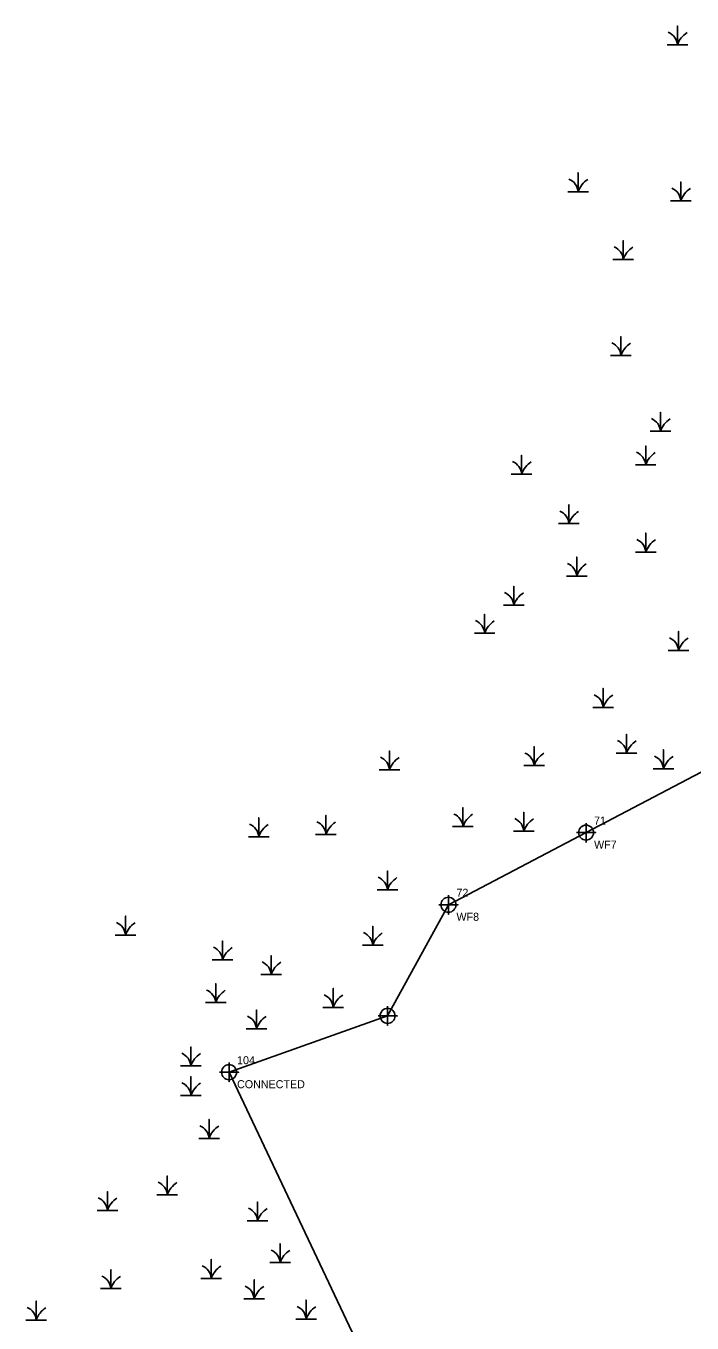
# Model space of a CAD drawing. Extents: x 2189822 to 2190837, y 387253 to 388663.
# Drawn here: x 2189966.4 to 2190174.5, y 387688.6 to 388093.7 of the extents above; entities that cross this region are included whole.
import ezdxf

# ---------------------------------------------------------------- set-up
doc = ezdxf.new("R2010")
doc.units = 0
for name, color, linetype in [('COGO Default Chain', 7, 'Continuous'), ('DTM Contours Major', 7, 'Continuous'), ('DTM Contours Minor', 7, 'Continuous'), ('Exist DTM Breakline Cogo Elevation', 7, 'Continuous'), ('Exist DTM Breakline Cogo Number', 7, 'Continuous')]:
    doc.layers.add(name, color=color, linetype=linetype)

msp = doc.modelspace()

# ---------------------------------------------------------------- linework, layer by layer
at = {"layer": 'DTM Contours Major'}
for points in [[(2190141.4, 387844.78), (2190141.4, 387838.78), (2190141.4, 387841.78), (2190144.4, 387841.78), (2190138.4, 387841.78)], [(2190098.41, 387822.25), (2190098.41, 387816.25), (2190098.41, 387819.25), (2190101.41, 387819.25), (2190095.41, 387819.25)], [(2190079.41, 387787.56), (2190079.41, 387781.56), (2190079.41, 387784.56), (2190082.41, 387784.56), (2190076.41, 387784.56)], [(2190029.88, 387769.97), (2190029.88, 387763.97), (2190029.88, 387766.97), (2190032.88, 387766.97), (2190026.88, 387766.97)]]:
    msp.add_lwpolyline(points, dxfattribs=at)
for centre in [(2190141.4, 387841.78), (2190098.41, 387819.25), (2190079.41, 387784.56), (2190029.88, 387766.97)]:
    msp.add_circle(centre, 2.34, dxfattribs=at)
at = {"layer": 'Exist DTM Breakline Cogo Elevation'}
for p, q in [((2190169.93, 388090.44), (2190169.93, 388090.44)), ((2190138.9, 388044.58), (2190138.9, 388044.58)), ((2190170.98, 388041.76), (2190170.98, 388041.76)), ((2190153, 388023.42), (2190153, 388023.42)), ((2190152.3, 387993.43), (2190152.3, 387993.43)), ((2190164.64, 387969.8), (2190164.64, 387969.8)), ((2190160.02, 387959.29), (2190160.02, 387959.29)), ((2190121.28, 387956.39), (2190121.28, 387956.39)), ((2190136.05, 387940.94), (2190136.05, 387940.94)), ((2190160.06, 387932.05), (2190160.06, 387932.05)), ((2190138.47, 387924.57), (2190138.47, 387924.57)), ((2190118.81, 387915.48), (2190118.81, 387915.48)), ((2190109.72, 387906.71), (2190109.72, 387906.71)), ((2190170.28, 387901.37), (2190170.28, 387901.37)), ((2190146.73, 387883.57), (2190146.73, 387883.57)), ((2190154.06, 387869.26), (2190154.06, 387869.26)), ((2190079.98, 387864.06), (2190079.98, 387864.06)), ((2190125.16, 387865.38), (2190125.16, 387865.38)), ((2190165.57, 387864.39), (2190165.57, 387864.39)), ((2190102.95, 387846.34), (2190102.95, 387846.34)), ((2190039.14, 387843.16), (2190039.14, 387843.16)), ((2190060.16, 387843.9), (2190060.16, 387843.9)), ((2190121.95, 387844.89), (2190121.95, 387844.89)), ((2190079.33, 387826.58), (2190079.33, 387826.58)), ((2189997.54, 387812.47), (2189997.54, 387812.47)), ((2190074.74, 387809.3), (2190074.74, 387809.3)), ((2190027.86, 387804.71), (2190027.86, 387804.71)), ((2190043.02, 387800.13), (2190043.02, 387800.13)), ((2190025.71, 387791.38), (2190025.71, 387791.38)), ((2190062.41, 387789.9), (2190062.41, 387789.9)), ((2190038.43, 387783.19), (2190038.43, 387783.19)), ((2190017.95, 387771.62), (2190017.95, 387771.62)), ((2190017.99, 387762.38), (2190017.99, 387762.38)), ((2190023.63, 387748.98), (2190023.63, 387748.98)), ((2190010.58, 387731.34), (2190010.58, 387731.34)), ((2189991.86, 387726.47), (2189991.86, 387726.47)), ((2190038.79, 387723.23), (2190038.79, 387723.23)), ((2190045.84, 387710.17), (2190045.84, 387710.17)), ((2190024.33, 387705.24), (2190024.33, 387705.24)), ((2189992.96, 387702.06), (2189992.96, 387702.06)), ((2190037.73, 387698.89), (2190037.73, 387698.89)), ((2189969.65, 387692.25), (2189969.65, 387692.25)), ((2190053.95, 387692.54), (2190053.95, 387692.54))]:
    msp.add_line(p, q, dxfattribs=at)
for points in [[(2190166.7, 388087.77), (2190169.93, 388087.77), (2190169.93, 388093.68), (2190169.93, 388087.77), (2190173.15, 388087.77)], [(2190135.68, 388041.91), (2190138.9, 388041.91), (2190138.9, 388047.83), (2190138.9, 388041.91), (2190142.13, 388041.91)], [(2190167.76, 388039.09), (2190170.98, 388039.09), (2190170.98, 388045), (2190170.98, 388039.09), (2190174.21, 388039.09)], [(2190149.78, 388020.74), (2190153.01, 388020.74), (2190153.01, 388026.66), (2190153.01, 388020.74), (2190156.23, 388020.74)], [(2190149.07, 387990.76), (2190152.3, 387990.76), (2190152.3, 387996.68), (2190152.3, 387990.76), (2190155.53, 387990.76)], [(2190161.41, 387967.12), (2190164.64, 387967.12), (2190164.64, 387973.04), (2190164.64, 387967.12), (2190167.86, 387967.12)], [(2190118.05, 387953.72), (2190121.28, 387953.72), (2190121.28, 387959.64), (2190121.28, 387953.72), (2190124.5, 387953.72)], [(2190156.79, 387956.61), (2190160.02, 387956.61), (2190160.02, 387962.53), (2190160.02, 387956.61), (2190163.24, 387956.61)], [(2190132.82, 387938.27), (2190136.05, 387938.27), (2190136.05, 387944.19), (2190136.05, 387938.27), (2190139.27, 387938.27)], [(2190156.83, 387929.38), (2190160.06, 387929.38), (2190160.06, 387935.3), (2190160.06, 387929.38), (2190163.28, 387929.38)], [(2190135.25, 387921.89), (2190138.47, 387921.89), (2190138.47, 387927.81), (2190138.47, 387921.89), (2190141.7, 387921.89)], [(2190115.59, 387912.8), (2190118.81, 387912.8), (2190118.81, 387918.72), (2190118.81, 387912.8), (2190122.04, 387912.8)], [(2190106.5, 387904.04), (2190109.72, 387904.04), (2190109.72, 387909.96), (2190109.72, 387904.04), (2190112.95, 387904.04)], [(2190167.05, 387898.69), (2190170.28, 387898.69), (2190170.28, 387904.61), (2190170.28, 387898.69), (2190173.5, 387898.69)], [(2190143.51, 387880.9), (2190146.73, 387880.9), (2190146.73, 387886.81), (2190146.73, 387880.9), (2190149.96, 387880.9)], [(2190150.84, 387866.59), (2190154.06, 387866.59), (2190154.06, 387872.51), (2190154.06, 387866.59), (2190157.29, 387866.59)], [(2190076.76, 387861.39), (2190079.98, 387861.39), (2190079.98, 387867.31), (2190079.98, 387861.39), (2190083.21, 387861.39)], [(2190121.93, 387862.71), (2190125.16, 387862.71), (2190125.16, 387868.63), (2190125.16, 387862.71), (2190128.38, 387862.71)], [(2190162.34, 387861.72), (2190165.57, 387861.72), (2190165.57, 387867.64), (2190165.57, 387861.72), (2190168.79, 387861.72)], [(2190099.72, 387843.66), (2190102.95, 387843.66), (2190102.95, 387849.58), (2190102.95, 387843.66), (2190106.17, 387843.66)], [(2190035.91, 387840.49), (2190039.14, 387840.49), (2190039.14, 387846.4), (2190039.14, 387840.49), (2190042.37, 387840.49)], [(2190056.93, 387841.22), (2190060.16, 387841.22), (2190060.16, 387847.14), (2190060.16, 387841.22), (2190063.38, 387841.22)], [(2190118.72, 387842.21), (2190121.95, 387842.21), (2190121.95, 387848.13), (2190121.95, 387842.21), (2190125.18, 387842.21)], [(2190076.1, 387823.91), (2190079.33, 387823.91), (2190079.33, 387829.83), (2190079.33, 387823.91), (2190082.55, 387823.91)], [(2189994.32, 387809.8), (2189997.54, 387809.8), (2189997.54, 387815.72), (2189997.54, 387809.8), (2190000.77, 387809.8)], [(2190071.52, 387806.62), (2190074.75, 387806.62), (2190074.75, 387812.54), (2190074.75, 387806.62), (2190077.97, 387806.62)], [(2190024.63, 387802.04), (2190027.86, 387802.04), (2190027.86, 387807.95), (2190027.86, 387802.04), (2190031.08, 387802.04)], [(2190039.79, 387797.45), (2190043.02, 387797.45), (2190043.02, 387803.37), (2190043.02, 387797.45), (2190046.24, 387797.45)], [(2190022.48, 387788.7), (2190025.71, 387788.7), (2190025.71, 387794.62), (2190025.71, 387788.7), (2190028.93, 387788.7)], [(2190059.18, 387787.22), (2190062.41, 387787.22), (2190062.41, 387793.14), (2190062.41, 387787.22), (2190065.63, 387787.22)], [(2190035.21, 387780.52), (2190038.43, 387780.52), (2190038.43, 387786.44), (2190038.43, 387780.52), (2190041.66, 387780.52)], [(2190014.73, 387768.95), (2190017.95, 387768.95), (2190017.95, 387774.86), (2190017.95, 387768.95), (2190021.18, 387768.95)], [(2190014.76, 387759.71), (2190017.99, 387759.71), (2190017.99, 387765.62), (2190017.99, 387759.71), (2190021.21, 387759.71)], [(2190020.4, 387746.3), (2190023.63, 387746.3), (2190023.63, 387752.22), (2190023.63, 387746.3), (2190026.85, 387746.3)], [(2190007.36, 387728.66), (2190010.59, 387728.66), (2190010.59, 387734.58), (2190010.59, 387728.66), (2190013.81, 387728.66)], [(2189988.64, 387723.79), (2189991.86, 387723.79), (2189991.86, 387729.71), (2189991.86, 387723.79), (2189995.09, 387723.79)], [(2190035.56, 387720.55), (2190038.79, 387720.55), (2190038.79, 387726.47), (2190038.79, 387720.55), (2190042.01, 387720.55)], [(2190042.61, 387707.5), (2190045.84, 387707.5), (2190045.84, 387713.42), (2190045.84, 387707.5), (2190049.06, 387707.5)], [(2190021.11, 387702.56), (2190024.33, 387702.56), (2190024.33, 387708.48), (2190024.33, 387702.56), (2190027.56, 387702.56)], [(2189989.73, 387699.39), (2189992.96, 387699.39), (2189992.96, 387705.3), (2189992.96, 387699.39), (2189996.18, 387699.39)], [(2190034.5, 387696.21), (2190037.73, 387696.21), (2190037.73, 387702.13), (2190037.73, 387696.21), (2190040.96, 387696.21)], [(2190050.72, 387689.86), (2190053.95, 387689.86), (2190053.95, 387695.78), (2190053.95, 387689.86), (2190057.17, 387689.86)], [(2189966.43, 387689.58), (2189969.66, 387689.58), (2189969.66, 387695.5), (2189969.66, 387689.58), (2189972.88, 387689.58)]]:
    msp.add_lwpolyline(points, dxfattribs=at)
for centre, radius, start, end in [((2190165.33, 388087.43), 4.61, 4.1403, 67.535), ((2190176.77, 388085.49), 7.21, 122.1274, 161.6222), ((2190134.3, 388041.57), 4.61, 4.1403, 67.535), ((2190145.75, 388039.64), 7.21, 122.1274, 161.6222), ((2190166.38, 388038.75), 4.61, 4.1403, 67.535), ((2190177.83, 388036.81), 7.21, 122.1274, 161.6222), ((2190148.41, 388020.41), 4.61, 4.1403, 67.535), ((2190159.85, 388018.47), 7.21, 122.1274, 161.6222), ((2190147.7, 387990.43), 4.61, 4.1403, 67.535), ((2190159.14, 387988.49), 7.21, 122.1274, 161.6222), ((2190160.04, 387966.79), 4.61, 4.1403, 67.535), ((2190171.48, 387964.85), 7.21, 122.1274, 161.6222), ((2190155.42, 387956.28), 4.61, 4.1403, 67.535), ((2190166.86, 387954.34), 7.21, 122.1274, 161.6222), ((2190116.68, 387953.39), 4.61, 4.1403, 67.535), ((2190128.12, 387951.45), 7.21, 122.1274, 161.6222), ((2190131.45, 387937.93), 4.61, 4.1403, 67.535), ((2190142.89, 387936), 7.21, 122.1274, 161.6222), ((2190155.46, 387929.05), 4.61, 4.1403, 67.535), ((2190166.9, 387927.11), 7.21, 122.1274, 161.6222), ((2190133.87, 387921.56), 4.61, 4.1403, 67.535), ((2190145.31, 387919.62), 7.21, 122.1274, 161.6222), ((2190114.21, 387912.47), 4.61, 4.1403, 67.535), ((2190125.65, 387910.53), 7.21, 122.1274, 161.6222), ((2190105.12, 387903.71), 4.61, 4.1403, 67.535), ((2190116.56, 387901.77), 7.21, 122.1274, 161.6222), ((2190165.68, 387898.36), 4.61, 4.1403, 67.535), ((2190177.12, 387896.42), 7.21, 122.1274, 161.6222), ((2190142.13, 387880.56), 4.61, 4.1403, 67.535), ((2190153.57, 387878.62), 7.21, 122.1274, 161.6222), ((2190149.46, 387866.26), 4.61, 4.1403, 67.535), ((2190160.9, 387864.32), 7.21, 122.1274, 161.6222), ((2190120.56, 387862.38), 4.61, 4.1403, 67.535), ((2190132, 387860.44), 7.21, 122.1274, 161.6222), ((2190160.97, 387861.39), 4.61, 4.1403, 67.535), ((2190075.38, 387861.06), 4.61, 4.1403, 67.535), ((2190086.82, 387859.12), 7.21, 122.1274, 161.6222), ((2190172.41, 387859.45), 7.21, 122.1274, 161.6222), ((2190098.35, 387843.33), 4.61, 4.1403, 67.535), ((2190109.79, 387841.39), 7.21, 122.1274, 161.6222), ((2190117.35, 387841.88), 4.61, 4.1403, 67.535), ((2190128.79, 387839.94), 7.21, 122.1274, 161.6222), ((2190034.54, 387840.15), 4.61, 4.1403, 67.535), ((2190045.98, 387838.21), 7.21, 122.1274, 161.6222), ((2190055.56, 387840.89), 4.61, 4.1403, 67.535), ((2190067, 387838.95), 7.21, 122.1274, 161.6222), ((2190074.73, 387823.57), 4.61, 4.1403, 67.535), ((2190086.17, 387821.63), 7.21, 122.1274, 161.6222), ((2189992.94, 387809.46), 4.61, 4.1403, 67.535), ((2190004.38, 387807.52), 7.21, 122.1274, 161.6222), ((2190070.15, 387806.29), 4.61, 4.1403, 67.535), ((2190081.59, 387804.35), 7.21, 122.1274, 161.6222), ((2190023.26, 387801.7), 4.61, 4.1403, 67.535), ((2190034.7, 387799.76), 7.21, 122.1274, 161.6222), ((2190038.42, 387797.12), 4.61, 4.1403, 67.535), ((2190049.86, 387795.18), 7.21, 122.1274, 161.6222), ((2190021.11, 387788.37), 4.61, 4.1403, 67.535), ((2190032.55, 387786.43), 7.21, 122.1274, 161.6222), ((2190057.81, 387786.89), 4.61, 4.1403, 67.535), ((2190069.25, 387784.95), 7.21, 122.1274, 161.6222), ((2190033.84, 387780.19), 4.61, 4.1403, 67.535), ((2190045.28, 387778.25), 7.21, 122.1274, 161.6222), ((2190013.35, 387768.61), 4.61, 4.1403, 67.535), ((2190024.79, 387766.67), 7.21, 122.1274, 161.6222), ((2190013.39, 387759.37), 4.61, 4.1403, 67.535), ((2190024.83, 387757.43), 7.21, 122.1274, 161.6222), ((2190019.03, 387745.97), 4.61, 4.1403, 67.535), ((2190030.47, 387744.03), 7.21, 122.1274, 161.6222), ((2190005.99, 387728.33), 4.61, 4.1403, 67.535), ((2190017.43, 387726.39), 7.21, 122.1274, 161.6222), ((2189987.26, 387723.46), 4.61, 4.1403, 67.535), ((2189998.71, 387721.52), 7.21, 122.1274, 161.6222), ((2190034.19, 387720.22), 4.61, 4.1403, 67.535), ((2190045.63, 387718.28), 7.21, 122.1274, 161.6222), ((2190041.24, 387707.17), 4.61, 4.1403, 67.535), ((2190052.68, 387705.23), 7.21, 122.1274, 161.6222), ((2190019.73, 387702.23), 4.61, 4.1403, 67.535), ((2190031.17, 387700.29), 7.21, 122.1274, 161.6222), ((2189988.36, 387699.05), 4.61, 4.1403, 67.535), ((2189999.8, 387697.11), 7.21, 122.1274, 161.6222), ((2190033.13, 387695.88), 4.61, 4.1403, 67.535), ((2190044.57, 387693.94), 7.21, 122.1274, 161.6222), ((2189965.06, 387689.24), 4.61, 4.1403, 67.535), ((2189976.5, 387687.31), 7.21, 122.1274, 161.6222), ((2190049.35, 387689.53), 4.61, 4.1403, 67.535), ((2190060.79, 387687.59), 7.21, 122.1274, 161.6222)]:
    msp.add_arc(centre, radius, start, end, dxfattribs=at)
at = {"layer": 'Exist DTM Breakline Cogo Number'}
for points in [[(2190311.6, 387912.32), (2190282.87, 387902.15), (2190276.9, 387926.61), (2190246.66, 387930.44), (2190212.31, 387905.81), (2190187.82, 387866.13), (2190141.4, 387841.78), (2190098.41, 387819.25)], [(2190098.41, 387819.25), (2190079.41, 387784.56), (2190029.88, 387766.97)], [(2190029.88, 387766.97), (2190072, 387678.13)]]:
    msp.add_lwpolyline(points, dxfattribs=at)

# ---------------------------------------------------------------- texts
at = {"layer": 'COGO Default Chain'}
for s, p in [('WF7', (2190143.9, 387836.78)), ('WF8', (2190100.91, 387814.25)), ('CONNECTED', (2190032.38, 387761.97))]:
    msp.add_text(s, height=2.5, dxfattribs=at).set_placement(p)
at = {"layer": 'DTM Contours Minor'}
for s, p in [('71', (2190143.9, 387844.28)), ('72', (2190100.91, 387821.75)), ('104', (2190032.38, 387769.47))]:
    msp.add_text(s, height=2.5, dxfattribs=at).set_placement(p)

doc.saveas('drawing.dxf')
